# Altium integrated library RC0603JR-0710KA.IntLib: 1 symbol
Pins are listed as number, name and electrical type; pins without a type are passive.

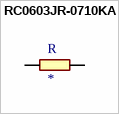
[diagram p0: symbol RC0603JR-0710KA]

## RC0603JR-0710KA
designator R
RESISTOR, THICK FILM, 10KOHM, 100mW, 5%; MF: Yageo; MP: RC0603JR-0710KA
footprint 0603
pins: 1, 2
